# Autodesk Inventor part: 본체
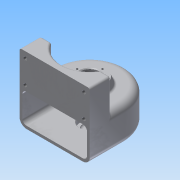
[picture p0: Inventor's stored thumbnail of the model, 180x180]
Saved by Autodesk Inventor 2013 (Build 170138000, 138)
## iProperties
Created: 2015-02
Part Number: 본체
Material: 알루미늄 6061
Document SubType Name: Modeling
Designer: Administrator
Density: 2.40731 g/cm^3
Mass: 510.936 g
Surface Area: 707.382 cm^2
Volume: 212.243 cm^3
Author: Administrator
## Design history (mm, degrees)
sketch "스케치1" dims "d0" = 100
  geometry: L1 (-50, -25)-(50, -25); L2 (50, -25)-(50, 25); L3 (50, 25)-(-50, 25); L4 (-50, 25)-(-50, -25); L5 (-50, -25)-(50, 25); L6 (50, -25)-(-50, 25); 2 further points
  constraints: 12 end point, 3 midpoint, 2 parallel, 1 horizontal, 1 horizontal alignment, 1 perpendicular, 2 other
  dimensions: "d3" = 50 distance of L1.end L2.end
extrude "돌출1" new body sketch "스케치1" distance "d4" = 50; taper "d5" = 0 deg
fillet "모깎기1" dims "d6" = 10
feature "쉘1" dims "d7" = 4
node "작업 평면1"
sketch "스케치2"
  geometry: L1 (-40, -25)-(-40, 25) reference; L2 (-40, -25)-(40, -25) reference; L3 (40, 25)-(40, -25) reference; L4 (50, -25)-(50, 25) reference; L5 (-50, 25)-(-50, -25) reference; L6 (-50, -25)-(50, -25); L7 (50, -25)-(50, 5); L8 (-50, 5)-(-50, -25); L9 (50, 5)-(34.641, 5); L10 (-34.641, 5)-(-50, 5); A1 r 40 centre (0, 25) between (40, 25) and (-40, 25) reference; A2 r 40 centre (0, 25) between (-34.641, 5) and (34.641, 5); 1 further point
  constraints: 11 end point, 3 parallel, 2 point on circle, 1 centre point, 1 coincident, 1 collinear, 1 horizontal, 1 perpendicular, 1 point on line
  dimensions: "d11" = 30 distance of L6.end L7.end; "d12" = 40 radius of A2
extrude "돌출2" join sketch "스케치2" stored distance "d13" = 50; taper "d14" = 0 deg
sketch "스케치3"
  geometry: C1 r 25 at (0, 25); A1 r 40 centre (0, 25) between (-34.641, 5) and (34.641, 5) reference; 1 further point
  constraints: 1 centre point, 1 coincident
  dimensions: "d15" = 50 diameter of C1
extrude "돌출3" join sketch "스케치3" distance "d17" = 10; taper "d18" = -20 deg
sketch "스케치4"
  geometry: C1 r 20 at (0, 25); A1 r 40 centre (0, 25) between (40, 25) and (-40, 25) reference; 1 further point
  constraints: 1 centre point, 1 coincident
  dimensions: "d19" = 40 diameter of C1
extrude "돌출4" join sketch "스케치4" distance "d21" = 9; taper "d22" = 0 deg
hole "구멍1" diameter "d25" = 20; stored, may be unused: countersink angle "d29" = 90 deg, drill point angle "d31" = 118 deg; dims "d23" = 10, "d24" = 10, "d26" = 6, "d27" = 28, "d28" = 10, "d30" = 8
hole "구멍2" diameter "d34" = 20; stored, may be unused: countersink angle "d38" = 90 deg, drill point angle "d40" = 0 deg; dims "d32" = 10, "d33" = 10, "d35" = 6, "d36" = 28, "d37" = 8, "d39" = 10
sketch "스케치5"
  geometry: C1 r 14 at (0, 0) reference; C2 r 21.36 at (0, 0) reference; A1 r 18 centre (0, 0) between (0, 18) and (0, -18); 3 further points
  constraints: 4 point on circle, 2 horizontal alignment, 2 vertical alignment, 1 centre point, 1 coincident
  dimensions: "d41" = 36 diameter of A1
hole "구멍3" sketch "스케치5" at (0, 18), (0, -18), (-18, 0), (18, 0) diameter "d43" = 2.459; stored, may be unused: countersink angle "d47" = 90 deg, drill point angle "d49" = 118 deg; dims "d44" = 6, "d45" = 28, "d46" = 8, "d48" = 9
sketch "스케치6"
  geometry: L1 (-10, 95)-(90, 95) reference; L2 (-1.75, 53)-(81.75, 53); L3 (81.75, 53)-(81.75, 86); L4 (81.75, 86)-(-1.75, 86); L5 (-1.75, 86)-(-1.75, 53); 7 further points
  constraints: 8 end point, 4 coincident, 2 midpoint, 2 parallel, 1 horizontal, 1 perpendicular, 1 vertical alignment
  dimensions: "d50" = 83.5 distance of L3.end L4.end; "d52" = 33 distance of L2.end L3.end; "d53" = 9 distance between parallel lines of L4 L1
hole "구멍4" sketch "스케치6" at (-1.75, 86), (-1.75, 53), (81.75, 53), (81.75, 86) diameter "d54" = 5.134; stored, may be unused: countersink angle "d58" = 90 deg, drill point angle "d60" = 118 deg; dims "d55" = 10, "d56" = 28, "d57" = 8, "d59" = 13
node "작업 평면2"
sketch "스케치7"
  geometry: 2 further points
  constraints: 1 vertical alignment, 1 other
  dimensions: "d61" = 25 distance of point (0, 0) point (0, 25)
feature "엠보싱1" sketch "스케치7" dims "d62" = 0.5, "d63" = 0
fillet "모깎기2" dims "d64" = 3, "d65" = 0.3
fillet "모깎기3" dims "d66" = 3
chamfer "모따기1" distance "d67" = 1; stored, may be unused: second distance "d68" = 2, angle "d69" = 45 deg
node "솔리드1"
node "투영된 루프1"
other parameters: "d8" = 45
